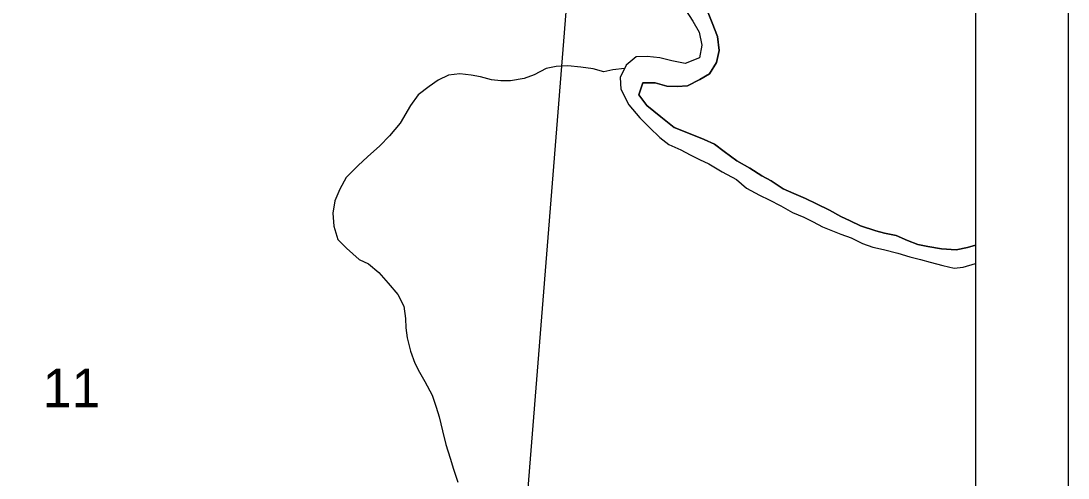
# Model space of a CAD drawing. Extents: x 0 to 34, y 0 to 22.
# Drawn here: x 7.868 to 9, y 17.019 to 17.514 of the extents above; entities that cross this region are included whole.
import ezdxf

# ---------------------------------------------------------------- set-up
doc = ezdxf.new("R2010")
doc.units = 0
for name, color, linetype in [('GM_X_Corporation', 7, 'Continuous'), ('GM_X_Major_River', 7, 'Continuous'), ('GM_X_Minor_River', 7, 'Continuous'), ('GM_X_Section_Text', 7, 'Continuous'), ('SH_Data', 7, 'Continuous')]:
    doc.layers.add(name, color=color, linetype=linetype)

msp = doc.modelspace()

# ---------------------------------------------------------------- linework, layer by layer
at = {"layer": 'GM_X_Corporation'}
msp.add_lwpolyline([(8.4629, 17.601), (8.3827, 16.5919), (7.3858, 16.6558), (7.4643, 17.6703)], close=True, dxfattribs=at)
at = {"layer": 'GM_X_Major_River'}
for p, q in [((8.5856, 17.5269), (8.5941, 17.5137)), ((8.6153, 17.5116), (8.6102, 17.5244)), ((8.5941, 17.5137), (8.601, 17.5016)), ((8.6211, 17.4969), (8.6153, 17.5116)), ((8.601, 17.5016), (8.6038, 17.4876)), ((8.6227, 17.4817), (8.6211, 17.4969)), ((8.6038, 17.4876), (8.6016, 17.474)), ((8.5331, 17.4749), (8.5222, 17.466)), ((8.5448, 17.4753), (8.5331, 17.4749)), ((8.5585, 17.4739), (8.5448, 17.4753)), ((8.5714, 17.4707), (8.5585, 17.4739)), ((8.6016, 17.474), (8.5861, 17.4678)), ((8.6198, 17.4688), (8.6227, 17.4817)), ((8.5222, 17.466), (8.5155, 17.4527)), ((8.5861, 17.4678), (8.5714, 17.4707)), ((8.6123, 17.4566), (8.6198, 17.4688)), ((8.5155, 17.4527), (8.5164, 17.4398)), ((8.5886, 17.4435), (8.6018, 17.4505)), ((8.6018, 17.4505), (8.6123, 17.4566)), ((8.5164, 17.4398), (8.5252, 17.4229)), ((8.5357, 17.4336), (8.5402, 17.4469)), ((8.5402, 17.4469), (8.5534, 17.4466)), ((8.5534, 17.4466), (8.5663, 17.4433)), ((8.5663, 17.4433), (8.5773, 17.4427)), ((8.5773, 17.4427), (8.5886, 17.4435)), ((8.5445, 17.4223), (8.5357, 17.4336)), ((8.5252, 17.4229), (8.5371, 17.409)), ((8.5598, 17.4099), (8.5445, 17.4223)), ((8.5371, 17.409), (8.5474, 17.3984)), ((8.5739, 17.3983), (8.5598, 17.4099)), ((8.5474, 17.3984), (8.5585, 17.3876)), ((8.5948, 17.3902), (8.5739, 17.3983)), ((8.5585, 17.3876), (8.5684, 17.3801)), ((8.6065, 17.3853), (8.5948, 17.3902)), ((8.6175, 17.3805), (8.6065, 17.3853)), ((8.5684, 17.3801), (8.5813, 17.3741)), ((8.5813, 17.3741), (8.5915, 17.3689)), ((8.6282, 17.3723), (8.6175, 17.3805)), ((8.6419, 17.3622), (8.6282, 17.3723)), ((8.5915, 17.3689), (8.6014, 17.3637)), ((8.6014, 17.3637), (8.6117, 17.3592)), ((8.6117, 17.3592), (8.6261, 17.3503)), ((8.656, 17.3543), (8.6419, 17.3622)), ((8.6261, 17.3503), (8.6413, 17.3421)), ((8.6689, 17.3461), (8.656, 17.3543)), ((8.6413, 17.3421), (8.6524, 17.3327)), ((8.6788, 17.3405), (8.6689, 17.3461)), ((8.6921, 17.3319), (8.6788, 17.3405)), ((8.6524, 17.3327), (8.6665, 17.3253)), ((8.6665, 17.3253), (8.6767, 17.32)), ((8.7035, 17.3271), (8.6921, 17.3319)), ((8.7161, 17.3215), (8.7035, 17.3271)), ((8.6767, 17.32), (8.6893, 17.3137)), ((8.6893, 17.3137), (8.7022, 17.3063)), ((8.7278, 17.3156), (8.7161, 17.3215)), ((8.7419, 17.3089), (8.7278, 17.3156)), ((8.7022, 17.3063), (8.7143, 17.3014)), ((8.7544, 17.3022), (8.7419, 17.3089)), ((8.7643, 17.2973), (8.7544, 17.3022)), ((8.7143, 17.3014), (8.7242, 17.2962)), ((8.7242, 17.2962), (8.7345, 17.291)), ((8.7345, 17.291), (8.7542, 17.2829)), ((8.7757, 17.2921), (8.7643, 17.2973)), ((8.792, 17.2866), (8.7757, 17.2921)), ((8.7542, 17.2829), (8.7656, 17.2788)), ((8.8015, 17.284), (8.792, 17.2866)), ((8.814, 17.2815), (8.8015, 17.284)), ((8.8262, 17.2759), (8.814, 17.2815)), ((8.7656, 17.2788), (8.7778, 17.2728)), ((8.7778, 17.2728), (8.7888, 17.2688)), ((8.7888, 17.2688), (8.8005, 17.2662)), ((8.8376, 17.2719), (8.8262, 17.2759)), ((8.8482, 17.2697), (8.8376, 17.2719)), ((8.863, 17.2672), (8.8482, 17.2697)), ((8.8913, 17.2686), (8.8789, 17.2658)), ((8.9, 17.2709), (8.8913, 17.2686)), ((8.8005, 17.2662), (8.8161, 17.2622)), ((8.8161, 17.2622), (8.829, 17.2585)), ((8.829, 17.2585), (8.8404, 17.2556)), ((8.8789, 17.2658), (8.863, 17.2672)), ((8.8404, 17.2556), (8.851, 17.2527)), ((8.851, 17.2527), (8.8646, 17.249)), ((8.8646, 17.249), (8.8768, 17.2461)), ((8.8768, 17.2461), (8.8866, 17.2473)), ((8.8866, 17.2473), (8.9, 17.2512))]:
    msp.add_line(p, q, dxfattribs=at)
for points in [[(8.5856, 17.5269), (8.5941, 17.5137), (8.601, 17.5016), (8.6038, 17.4876), (8.6016, 17.474), (8.5861, 17.4678), (8.5714, 17.4707), (8.5585, 17.4739), (8.5448, 17.4753), (8.5331, 17.4749), (8.5222, 17.466), (8.5155, 17.4527), (8.5164, 17.4398), (8.5252, 17.4229), (8.5371, 17.409), (8.5474, 17.3984), (8.5585, 17.3876), (8.5684, 17.3801), (8.5813, 17.3741), (8.5915, 17.3689), (8.6014, 17.3637), (8.6117, 17.3592), (8.6261, 17.3503), (8.6413, 17.3421), (8.6524, 17.3327), (8.6665, 17.3253), (8.6767, 17.32), (8.6893, 17.3137), (8.7022, 17.3063), (8.7143, 17.3014), (8.7242, 17.2962), (8.7345, 17.291), (8.7542, 17.2829), (8.7656, 17.2788), (8.7778, 17.2728), (8.7888, 17.2688), (8.8005, 17.2662), (8.8161, 17.2622), (8.829, 17.2585), (8.8404, 17.2556), (8.851, 17.2527), (8.8646, 17.249), (8.8768, 17.2461), (8.8866, 17.2473), (8.9, 17.2512)], [(8.6102, 17.5244), (8.6153, 17.5116), (8.6211, 17.4969), (8.6227, 17.4817), (8.6198, 17.4688), (8.6123, 17.4566), (8.6018, 17.4505), (8.5886, 17.4435), (8.5773, 17.4427), (8.5663, 17.4433), (8.5534, 17.4466), (8.5402, 17.4469), (8.5357, 17.4336), (8.5445, 17.4223), (8.5598, 17.4099), (8.5739, 17.3983), (8.5948, 17.3902), (8.6065, 17.3853), (8.6175, 17.3805), (8.6282, 17.3723), (8.6419, 17.3622), (8.656, 17.3543), (8.6689, 17.3461), (8.6788, 17.3405), (8.6921, 17.3319), (8.7035, 17.3271), (8.7161, 17.3215), (8.7278, 17.3156), (8.7419, 17.3089), (8.7544, 17.3022), (8.7643, 17.2973), (8.7757, 17.2921), (8.792, 17.2866), (8.8015, 17.284), (8.814, 17.2815), (8.8262, 17.2759), (8.8376, 17.2719), (8.8482, 17.2697), (8.863, 17.2672), (8.8789, 17.2658), (8.8913, 17.2686), (8.9, 17.2709)]]:
    msp.add_lwpolyline(points, dxfattribs=at)
at = {"layer": 'GM_X_Minor_River'}
for p, q in [((8.4356, 17.4622), (8.4228, 17.4553)), ((8.4465, 17.4646), (8.4356, 17.4622)), ((8.459, 17.4651), (8.4465, 17.4646)), ((8.473, 17.4637), (8.459, 17.4651)), ((8.4863, 17.4619), (8.473, 17.4637)), ((8.4981, 17.4586), (8.4863, 17.4619)), ((8.5079, 17.461), (8.4981, 17.4586)), ((8.5203, 17.4622), (8.5079, 17.461)), ((8.3188, 17.4498), (8.309, 17.4429)), ((8.3301, 17.4552), (8.3188, 17.4498)), ((8.3422, 17.4564), (8.3301, 17.4552)), ((8.3547, 17.455), (8.3422, 17.4564)), ((8.3645, 17.4532), (8.3547, 17.455)), ((8.3767, 17.4499), (8.3645, 17.4532)), ((8.3865, 17.4489), (8.3767, 17.4499)), ((8.3971, 17.449), (8.3865, 17.4489)), ((8.4119, 17.4514), (8.3971, 17.449)), ((8.4228, 17.4553), (8.4119, 17.4514)), ((8.309, 17.4429), (8.2974, 17.4337)), ((8.2974, 17.4337), (8.2888, 17.4222)), ((8.2888, 17.4222), (8.2776, 17.4032)), ((8.2776, 17.4032), (8.2663, 17.3894)), ((8.2663, 17.3894), (8.2558, 17.3784)), ((8.2558, 17.3784), (8.2423, 17.3665)), ((8.2423, 17.3665), (8.2322, 17.3573)), ((8.2322, 17.3573), (8.2194, 17.3443)), ((8.2194, 17.3443), (8.2124, 17.3317)), ((8.2124, 17.3317), (8.2072, 17.3192)), ((8.2072, 17.3192), (8.205, 17.3055)), ((8.205, 17.3055), (8.2059, 17.2915)), ((8.2059, 17.2915), (8.2102, 17.2771)), ((8.2102, 17.2771), (8.2197, 17.2678)), ((8.2197, 17.2678), (8.2334, 17.2554)), ((8.2334, 17.2554), (8.2437, 17.2509)), ((8.2437, 17.2509), (8.2548, 17.2415)), ((8.2548, 17.2415), (8.2647, 17.2299)), ((8.2647, 17.2299), (8.2754, 17.2175)), ((8.2754, 17.2175), (8.2816, 17.205)), ((8.2816, 17.205), (8.2836, 17.1918)), ((8.2836, 17.1918), (8.284, 17.1816)), ((8.284, 17.1816), (8.2853, 17.1706)), ((8.2853, 17.1706), (8.2888, 17.1562)), ((8.2888, 17.1562), (8.2938, 17.1434)), ((8.2938, 17.1434), (8.2985, 17.1336)), ((8.2985, 17.1336), (8.3046, 17.1234)), ((8.3046, 17.1234), (8.3123, 17.1087)), ((8.3123, 17.1087), (8.3166, 17.0955)), ((8.3166, 17.0955), (8.3201, 17.0853)), ((8.3201, 17.0853), (8.3236, 17.0701)), ((8.3236, 17.0701), (8.3271, 17.0554)), ((8.3271, 17.0554), (8.3318, 17.0403)), ((8.3318, 17.0403), (8.3353, 17.0286)), ((8.3353, 17.0286), (8.34, 17.0146))]:
    msp.add_line(p, q, dxfattribs=at)
at = {"layer": 'SH_Data'}
for p, q in [((9, 21), (9, 14)), ((8.9, 20.9), (8.9, 14.1))]:
    msp.add_line(p, q, dxfattribs=at)

# ---------------------------------------------------------------- texts
at = {"layer": 'GM_X_Section_Text'}
msp.add_text('11', height=0.04186, rotation=0, dxfattribs=at).set_placement((7.8913, 17.0955))

doc.saveas('drawing.dxf')
